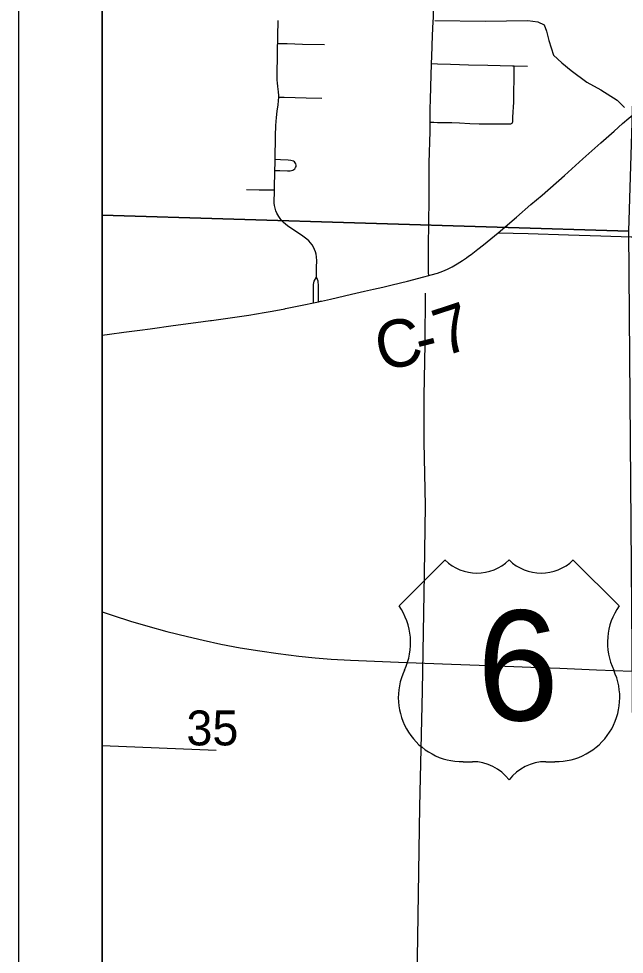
# Model space of a CAD drawing. Extents: x -59 to 43, y 0 to 22.
# Drawn here: x 23.417 to 24.142, y 15.472 to 16.594 of the extents above; entities that cross this region are included whole.
import ezdxf

# ---------------------------------------------------------------- set-up
doc = ezdxf.new("R2010")
doc.units = 0
for name, color, linetype in [('Default', 7, 'Continuous'), ('GM_X_City_Street', 7, 'Continuous'), ('GM_X_County_Road', 7, 'Continuous'), ('GM_X_County_Road_Text', 7, 'Continuous'), ('GM_X_Interchange_Ramps', 7, 'Continuous'), ('GM_X_Minor_River', 7, 'Continuous'), ('GM_X_Section_Text', 7, 'Continuous'), ('GM_X_Township_Road', 7, 'Continuous'), ('GM_X_US_Location', 7, 'Continuous'), ('GM_X_US_Route', 7, 'Continuous'), ('GM_X_US_Shield', 7, 'Continuous'), ('SH_Data', 7, 'Continuous')]:
    doc.layers.add(name, color=color, linetype=linetype)

msp = doc.modelspace()

# ---------------------------------------------------------------- linework, layer by layer
at = {"layer": 'Default'}
for points in [[(23.5167, 17.352), (23.5167, 16.3587), (24.1477, 16.3396), (24.1786, 17.3434), (23.6345, 17.3468)], [(23.5167, 16.3587), (23.5167, 15.3547), (24.1557, 15.3353), (24.1477, 16.3396)]]:
    msp.add_lwpolyline(points, close=True, dxfattribs=at)
at = {"layer": 'GM_X_City_Street'}
for points in [[(23.7734, 16.2841), (23.7736, 16.2962), (23.7737, 16.304), (23.7734, 16.3086), (23.7729, 16.3117), (23.7721, 16.3147), (23.771, 16.3176), (23.7697, 16.3204), (23.7681, 16.3231), (23.7663, 16.3256), (23.7642, 16.3279), (23.7619, 16.33), (23.7556, 16.3346), (23.744, 16.3424), (23.7389, 16.346), (23.7341, 16.3498), (23.7319, 16.352), (23.7299, 16.3545), (23.7282, 16.3571), (23.726, 16.3611), (23.7247, 16.364), (23.7238, 16.367), (23.7232, 16.37), (23.7228, 16.3731), (23.7227, 16.3762), (23.723, 16.3855), (23.723, 16.3888), (23.723, 16.3964), (23.7234, 16.4057), (23.7236, 16.4121), (23.7239, 16.4213), (23.724, 16.4254), (23.7244, 16.4539), (23.7248, 16.4663), (23.7255, 16.4756), (23.7264, 16.4834), (23.7277, 16.491), (23.7281, 16.4957), (23.7283, 16.5002), (23.7283, 16.5019), (23.7281, 16.5065), (23.7272, 16.5127), (23.7266, 16.5173), (23.7264, 16.5204), (23.7269, 16.5577), (23.7269, 16.5608), (23.7269, 16.5624), (23.727, 16.5645), (23.7272, 16.5732), (23.7276, 16.5919)], [(23.727, 16.5645), (23.7336, 16.5644), (23.7382, 16.5644), (23.7568, 16.5638), (23.7832, 16.5633)], [(23.7283, 16.5002), (23.7348, 16.5), (23.7612, 16.4993), (23.7798, 16.499)], [(23.7236, 16.4121), (23.7296, 16.412), (23.7389, 16.4118), (23.742, 16.4119), (23.7436, 16.4121), (23.745, 16.4126), (23.7464, 16.4133), (23.7476, 16.4143), (23.7485, 16.4156), (23.749, 16.417), (23.7491, 16.4185), (23.7488, 16.42), (23.7481, 16.4214), (23.747, 16.4225), (23.7458, 16.4233), (23.7443, 16.4239), (23.7428, 16.4243), (23.7397, 16.4247), (23.7304, 16.4251), (23.724, 16.4254)], [(23.6898, 16.3893), (23.7046, 16.3891), (23.7172, 16.3889), (23.723, 16.3888)], [(23.7699, 16.2536), (23.7699, 16.2605), (23.7698, 16.2705), (23.7699, 16.2753), (23.7708, 16.2793), (23.7734, 16.2841)], [(23.7757, 16.2549), (23.7757, 16.2627), (23.7757, 16.2738), (23.7753, 16.2794), (23.7747, 16.2815), (23.7734, 16.2841)]]:
    msp.add_lwpolyline(points, dxfattribs=at)
at = {"layer": 'GM_X_County_Road'}
msp.add_line((23.6477, 16.2325), (23.6505, 16.2329), dxfattribs=at)
for points in [[(23.9912, 16.3373), (24.013, 16.3564), (24.0303, 16.3712), (24.0437, 16.3826), (24.0707, 16.406), (24.0928, 16.426), (24.1142, 16.4453), (24.13, 16.4595), (24.1402, 16.4686), (24.1476, 16.4751), (24.15, 16.477), (24.1526, 16.4789), (24.1561, 16.4812), (24.1605, 16.4836)], [(23.9079, 16.2861), (23.9107, 16.2869), (23.9183, 16.2892), (23.9249, 16.2916), (23.9306, 16.294), (23.9361, 16.2968), (23.9422, 16.3002), (23.9486, 16.3044), (23.9533, 16.3075), (23.9558, 16.3094), (23.9588, 16.3116), (23.9667, 16.3177), (23.9735, 16.323), (23.9912, 16.3373)], [(23.831, 16.2673), (23.8418, 16.2698), (23.8528, 16.2722), (23.8643, 16.275), (23.8824, 16.2793), (23.9022, 16.2846), (23.9079, 16.2861)], [(23.7784, 16.2555), (23.7793, 16.2557), (23.7904, 16.258), (23.8155, 16.2638), (23.831, 16.2673)], [(23.6505, 16.2329), (23.6842, 16.2377), (23.6923, 16.2389), (23.7107, 16.2418), (23.7205, 16.2436), (23.7357, 16.2465), (23.7364, 16.2466), (23.7583, 16.2511), (23.7699, 16.2536)], [(23.7699, 16.2536), (23.7757, 16.2549), (23.7784, 16.2555)], [(23.5167, 16.2148), (23.5255, 16.2159), (23.5427, 16.2183), (23.5618, 16.2209), (23.5741, 16.2225), (23.6018, 16.2263), (23.6289, 16.2299), (23.6464, 16.2323), (23.6477, 16.2325)]]:
    msp.add_lwpolyline(points, dxfattribs=at)
at = {"layer": 'GM_X_Interchange_Ramps'}
msp.add_lwpolyline([(23.5167, 20.9), (23.5167, 15.3531)], dxfattribs=at)
at = {"layer": 'GM_X_Minor_River'}
msp.add_line((23.6533, 15.7169), (23.5167, 15.7222), dxfattribs=at)
for points in [[(23.9151, 16.5918), (23.9754, 16.5913), (24.0266, 16.5919), (24.0388, 16.5903), (24.0464, 16.5869), (24.049, 16.5793), (24.052, 16.5679), (24.0576, 16.5504), (24.0675, 16.5412), (24.0788, 16.5321), (24.0974, 16.518), (24.114, 16.5088), (24.1337, 16.4966), (24.1424, 16.4878)], [(23.8739, 14.2674), (23.879, 14.4615), (23.8775, 14.5785), (23.882, 14.811), (23.8872, 15.0176), (23.89, 15.2026), (23.8927, 15.3466), (23.8951, 15.4928), (23.8975, 15.6493), (23.9005, 15.7884), (23.9028, 15.9286), (23.9042, 16.0106), (23.9026, 16.0866), (23.9024, 16.1417), (23.9037, 16.2044), (23.9039, 16.2651)]]:
    msp.add_lwpolyline(points, dxfattribs=at)
at = {"layer": 'GM_X_Township_Road'}
msp.add_line((24.0105, 16.5376), (24.0265, 16.5371), dxfattribs=at)
for points in [[(23.9133, 16.5909), (23.9135, 16.5951), (23.9136, 16.5993), (23.9142, 16.6197), (23.9152, 16.6723)], [(23.9114, 16.5403), (23.9117, 16.5488), (23.9126, 16.574), (23.9133, 16.5909)], [(23.9096, 16.47), (23.9098, 16.4872), (23.91, 16.4961), (23.9105, 16.5134), (23.9109, 16.5255), (23.9114, 16.5403)], [(23.9114, 16.5403), (23.9185, 16.5401), (23.9339, 16.5395), (23.9556, 16.539), (23.9788, 16.5383), (24.0082, 16.5377), (24.0105, 16.5376)], [(24.008, 16.4688), (24.0085, 16.4696), (24.0088, 16.471), (24.0089, 16.4766), (24.0092, 16.4817), (24.0095, 16.4889), (24.0098, 16.4932), (24.0099, 16.4975), (24.01, 16.5024), (24.0101, 16.5074), (24.0101, 16.5121), (24.0103, 16.5162), (24.0105, 16.5231), (24.0105, 16.5346), (24.0105, 16.5376)], [(23.9079, 16.2861), (23.9078, 16.2898), (23.9076, 16.2941), (23.9076, 16.2987), (23.9075, 16.3113), (23.9077, 16.3222), (23.9081, 16.3486), (23.9083, 16.3782), (23.9083, 16.389), (23.9083, 16.3984), (23.9086, 16.4123), (23.9086, 16.4215), (23.9095, 16.459), (23.9096, 16.47)], [(23.9096, 16.47), (23.9141, 16.47), (23.9186, 16.4699), (23.9264, 16.4696), (23.9355, 16.4696), (23.9447, 16.4692), (23.9572, 16.4687), (23.9684, 16.4683), (23.9821, 16.4681), (23.9927, 16.468), (23.9989, 16.468), (24.0058, 16.4681), (24.0064, 16.4682), (24.008, 16.4688)], [(23.9912, 16.3373), (24.0271, 16.3366), (24.0755, 16.3352), (24.114, 16.3339), (24.1506, 16.3328), (24.1553, 16.3326)]]:
    msp.add_lwpolyline(points, dxfattribs=at)
at = {"layer": 'GM_X_US_Route'}
msp.add_lwpolyline([(23.5167, 15.883), (23.5299, 15.8785), (23.5506, 15.8719), (23.5714, 15.8657), (23.5942, 15.8595), (23.6189, 15.8533), (23.6376, 15.8489), (23.6589, 15.8444), (23.6821, 15.8399), (23.7054, 15.8362), (23.7275, 15.833), (23.7522, 15.8299), (23.7719, 15.8279), (23.7911, 15.8264), (23.8141, 15.8252), (23.8718, 15.8228), (23.9246, 15.8206), (23.9793, 15.8188), (24.0302, 15.8167), (24.065, 15.8156), (24.1091, 15.8137), (24.1512, 15.8121)], dxfattribs=at)
at = {"layer": 'GM_X_US_Shield'}
for p, q in [((23.9273, 15.9451), (23.8724, 15.8902)), ((24.1361, 15.8902), (24.0811, 15.9451)), ((23.9493, 15.7034), (23.9603, 15.7034)), ((24.0482, 15.7034), (24.0592, 15.7034))]:
    msp.add_line(p, q, dxfattribs=at)
for centre, radius, start, end in [((23.9658, 15.9844), 0.0549, 225.573, 314.427), ((24.0427, 15.9844), 0.0549, 225.573, 314.427), ((23.8094, 15.8461), 0.0769, 334.5471, 35.0009), ((24.1991, 15.8461), 0.0769, 144.9991, 205.4529), ((23.9484, 15.7803), 0.0769, 154.8319, 270.6383), ((24.06, 15.7803), 0.0769, 269.3617, 25.1681), ((23.9603, 15.6485), 0.0549, 36.8699, 90), ((24.0482, 15.6485), 0.0549, 90, 143.1301)]:
    msp.add_arc(centre, radius, start, end, dxfattribs=at)
at = {"layer": 'SH_Data'}
for points in [[(23.4167, 21), (30.4167, 21), (30.4167, 14), (23.4167, 14)], [(23.5167, 20.9), (30.3167, 20.9), (30.3167, 14.1), (23.5167, 14.1)]]:
    msp.add_lwpolyline(points, close=True, dxfattribs=at)

# ---------------------------------------------------------------- texts
at = {"layer": 'GM_X_County_Road_Text'}
for s, rotation, p in [('7', 18.2325, (23.9252, 16.1886)), ('C', 11.9874, (23.8504, 16.1715)), ('-', 14.0352, (23.8982, 16.1817))]:
    msp.add_text(s, height=0.0568, rotation=rotation, dxfattribs=at).set_placement(p)
at = {"layer": 'GM_X_Section_Text'}
msp.add_text('35', height=0.04186, rotation=0, dxfattribs=at).set_placement((23.6176, 15.7229))
at = {"layer": 'GM_X_US_Location'}
for s, p in [('0', (24.0041, 15.8178)), ('/', (24.0042, 15.8178))]:
    msp.add_text(s, height=0.000189, dxfattribs=at).set_placement(p)
msp.add_text('6', height=0.000189, rotation=0, dxfattribs=at).set_placement((23.9851, 15.7786))
at = {"layer": 'GM_X_US_Shield'}
msp.add_text('6', height=0.1318, dxfattribs=at).set_placement((23.9659, 15.7529))

doc.saveas('drawing.dxf')
